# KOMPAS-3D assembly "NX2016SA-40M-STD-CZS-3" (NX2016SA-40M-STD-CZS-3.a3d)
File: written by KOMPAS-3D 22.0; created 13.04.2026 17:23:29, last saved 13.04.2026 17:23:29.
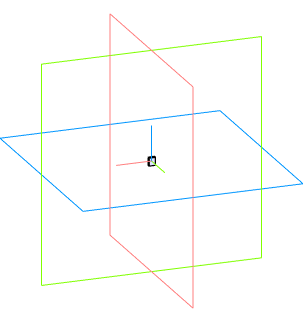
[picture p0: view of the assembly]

Document properties: Автор: Andrey; Полное имя файла: C:\Users\User1\Documents\NX2016SA-40M-STD-CZS-3.a3d

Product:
- Component [detail]: NX2016SA-40M-STD-CZS-3_NX2016SA-40M-STD-CZS-3  | qty 1  | source file: NX2016SA-40M-STD-CZS-3_NX2016SA-40M-STD-CZS-3.m3d
- Part/product: NX2016SA-40M-STD-CZS-3

Referenced files in C:\Users\User1\Documents\: NX2016SA-40M-STD-CZS-3_NX2016SA-40M-STD-CZS-3.m3d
